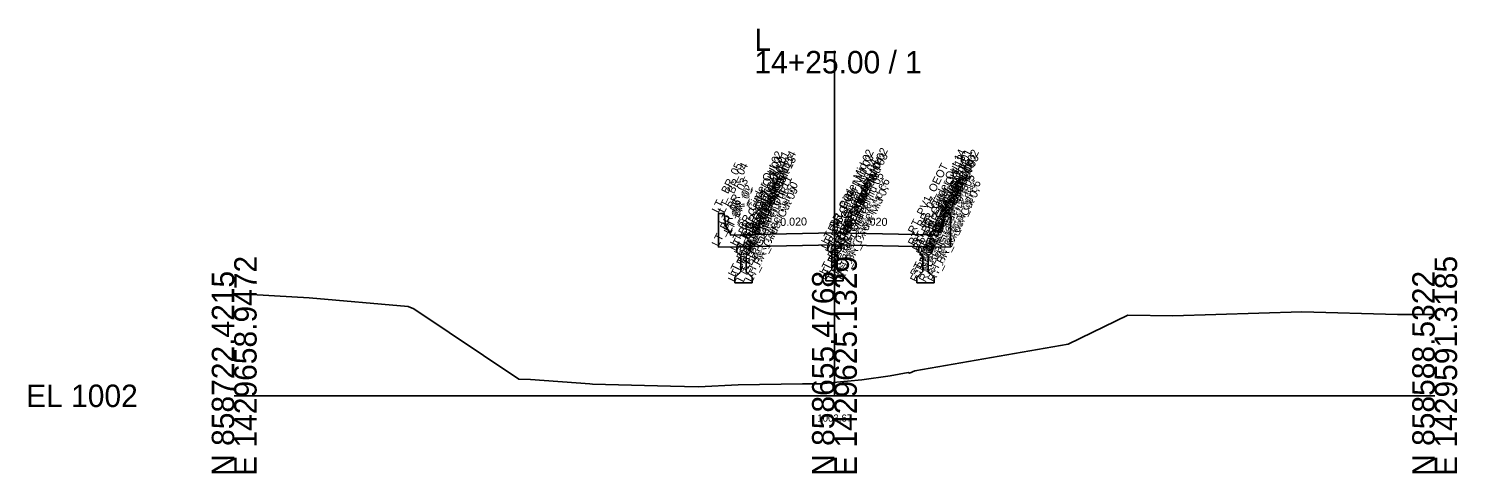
# Model space of a CAD drawing. Extents: x -26 to 153, y -10 to 13058.
# Drawn here: x -25.7 to 152.8, y 5490.3 to 5545.9 of the extents above; entities that cross this region are included whole.
import ezdxf

# ---------------------------------------------------------------- set-up
doc = ezdxf.new("R2010")
doc.units = 0
for name, color, linetype in [('Default', 7, 'Continuous'), ('Exist Cross Section Cell', 7, 'Continuous'), ('Exist XS Ground Line', 7, 'Continuous'), ('Prop CMT Concrete Structures', 7, 'Continuous'), ('Prop CMT Subgrade Daylight Point', 7, 'Continuous'), ('Prop XS Dump Level', 7, 'Continuous'), ('Prop XS SE Text', 7, 'Continuous')]:
    doc.layers.add(name, color=color, linetype=linetype)

msp = doc.modelspace()

# ---------------------------------------------------------------- linework, layer by layer
at = {"layer": 'Exist Cross Section Cell'}
for p, q in [((75, 5500), (75, 5543.08)), ((0, 5500), (75, 5500)), ((75, 5500), (150, 5500))]:
    msp.add_line(p, q, dxfattribs=at)
at = {"layer": 'Exist XS Ground Line'}
msp.add_lwpolyline([(0, 5512.79), (9.35, 5512.25), (21.72, 5511.16), (22.46, 5510.85), (35.55, 5502.07), (37.01, 5502.03), (44.44, 5501.49), (44.78, 5501.47), (54.52, 5501.19), (58.03, 5501.14), (62.99, 5501.38), (71.01, 5501.48), (73.39, 5501.51), (74.84, 5501.66), (78.42, 5502.01), (81.97, 5502.51), (84.22, 5502.92), (84.36, 5502.82), (85.04, 5503.11), (104.21, 5506.46), (111.64, 5510.06), (117.26, 5509.98), (133.39, 5510.5), (145.37, 5510.16), (149.53, 5510.15), (150, 5510.14)], dxfattribs=at)
at = {"layer": 'Prop CMT Concrete Structures'}
for points in [[(75, 5520.35), (65, 5520.15), (62, 5520.09), (61.99, 5520.34), (61.41, 5521.17), (61.24, 5522.76), (60.5, 5522.76), (60.5, 5518.56)], [(75, 5520.35), (85, 5520.15), (88, 5520.09), (88.01, 5520.34), (88.59, 5521.17), (88.76, 5522.76), (89.5, 5522.76), (89.5, 5518.56)], [(75, 5518.85), (75, 5520.35)], [(75, 5518.85), (75, 5520.35)], [(60.5, 5518.56), (65, 5518.65), (75, 5518.85)], [(64.46, 5518.64), (63.62, 5518.62), (62.79, 5518.61)], [(62.79, 5518.61), (62.79, 5517.96)], [(64.46, 5517.96), (64.46, 5518.64)], [(75, 5518.85), (74.17, 5518.83)], [(74.17, 5518.83), (74.17, 5518.18)], [(75, 5514.35), (75, 5518.85)], [(75, 5518.85), (75.83, 5518.83)], [(75, 5514.35), (75, 5518.85)], [(89.5, 5518.56), (85, 5518.65), (75, 5518.85)], [(75.83, 5518.83), (75.83, 5518.18)], [(85.54, 5518.64), (86.38, 5518.62), (87.21, 5518.61)], [(85.54, 5517.96), (85.54, 5518.64)], [(87.21, 5518.61), (87.21, 5517.96)], [(62.79, 5517.96), (63.29, 5517.46)], [(63.29, 5517.46), (63.29, 5515.54)], [(63.96, 5517.46), (64.46, 5517.96)], [(63.96, 5515.54), (63.96, 5517.46)], [(74.17, 5518.18), (74.67, 5517.68)], [(74.67, 5517.68), (74.67, 5515.77)], [(75.83, 5518.18), (75.33, 5517.68)], [(75.33, 5517.68), (75.33, 5515.77)], [(86.04, 5517.46), (85.54, 5517.96)], [(86.04, 5515.54), (86.04, 5517.46)], [(87.21, 5517.96), (86.71, 5517.46)], [(86.71, 5517.46), (86.71, 5515.54)], [(63.29, 5515.54), (62.54, 5514.79)], [(64.71, 5514.79), (63.96, 5515.54)], [(74.67, 5515.77), (73.92, 5515.02)], [(73.92, 5515.02), (73.92, 5514.35)], [(75.33, 5515.77), (76.08, 5515.02)], [(76.08, 5515.02), (76.08, 5514.35)], [(85.29, 5514.79), (86.04, 5515.54)], [(86.71, 5515.54), (87.46, 5514.79)], [(62.54, 5514.79), (62.54, 5514.12)], [(62.54, 5514.12), (63.62, 5514.12), (64.71, 5514.12)], [(64.71, 5514.12), (64.71, 5514.79)], [(73.92, 5514.35), (75, 5514.35)], [(76.08, 5514.35), (75, 5514.35)], [(85.29, 5514.12), (85.29, 5514.79)], [(87.46, 5514.12), (86.38, 5514.12), (85.29, 5514.12)], [(87.46, 5514.79), (87.46, 5514.12)]]:
    msp.add_lwpolyline(points, dxfattribs=at)

# ---------------------------------------------------------------- texts
at = {"layer": 'Default'}
msp.add_text('-', height=0.0001, dxfattribs=at).set_placement((0, 5500))
at = {"layer": 'Exist Cross Section Cell'}
for s, p in [('L', (65, 5543.08)), ('14+25.00 / 1', (65, 5540.28)), ('EL 1002', (-26, 5498.6))]:
    msp.add_text(s, height=2.8, dxfattribs=at).set_placement(p)
for s, p in [('E 1429658.9472', (2.8, 5490)), ('E 1429625.1329', (77.8, 5490)), ('E 1429591.3185', (152.8, 5490)), ('N 858722.4215', (0, 5490)), ('N 858655.4768', (75, 5490)), ('N 858588.5322', (150, 5490))]:
    msp.add_text(s, height=2.8, rotation=90, dxfattribs=at).set_placement(p)
at = {"layer": 'Prop CMT Subgrade Daylight Point'}
msp.add_text('1003.67', height=0.9, dxfattribs=at).set_placement((72.86, 5496.77))
at = {"layer": 'Prop XS Dump Level'}
for s, p in [('RT_BR_Girder Mid 02', (75.83, 5518.83)), ('LT_ BR_05', (60.5, 5522.76)), ('LT_BR_Girder Out 02', (62.79, 5518.61)), ('LT_BR_Girder Out 03', (62.79, 5517.96)), ('LT_BR_Girder Out 04', (63.29, 5517.46)), ('LT_BR_Girder Out 01', (63.62, 5518.62)), ('LT_BR_Girder Out 12', (63.96, 5517.46)), ('LT_BR_Girder Out 14', (64.46, 5518.64)), ('LT_BR_Girder Out 13', (64.46, 5517.96)), ('LT_BR_Girder Mid 02', (74.17, 5518.83)), ('LT_BR_Girder Mid 03', (74.17, 5518.18)), ('LT_BR_Girder Mid 04', (74.67, 5517.68)), ('RT_BR_Girder Mid 04', (75.33, 5517.68)), ('RT_BR_Girder Mid 03', (75.83, 5518.18)), ('RT_BR_Girder Out 14', (85.54, 5518.64)), ('RT_BR_Girder Out 13', (85.54, 5517.96)), ('RT_BR_Girder Out 12', (86.04, 5517.46)), ('RT_BR_Girder Out 01', (86.38, 5518.62)), ('RT_BR_Girder Out 04', (86.71, 5517.46)), ('RT_BR_Girder Out 02', (87.21, 5518.61)), ('RT_BR_Girder Out 03', (87.21, 5517.96)), ('RT_ BR_04', (88.76, 5522.76)), ('RT_ BR_05', (89.5, 5522.76)), ('LT_ BR_04', (61.24, 5522.76)), ('LT_BR_Girder Out 05', (63.29, 5515.54)), ('LT_BR_Girder Out 11', (63.96, 5515.54)), ('LT_PV1_OEOT', (65, 5520.15)), ('LT_BR_Girder Mid 05', (74.67, 5515.77)), ('RT_BR_Girder Mid 05', (75.33, 5515.77)), ('RT_PV1_OEOT', (85, 5520.15)), ('RT_BR_Girder Out 11', (86.04, 5515.54)), ('RT_BR_Girder Out 05', (86.71, 5515.54)), ('RT_BR_03', (88.59, 5521.17)), ('LT_BR_03', (61.41, 5521.17)), ('LT_BR_02', (61.99, 5520.34)), ('LT_BR_01', (62, 5520.09)), ('LT_BR_Girder Out 06', (62.54, 5514.79)), ('LT_BR_Girder Out 07', (62.54, 5514.12)), ('LT_BR_Girder Out 08', (63.62, 5514.12)), ('LT_BR_Girder Out 10', (64.71, 5514.79)), ('LT_BR_Girder Out 09', (64.71, 5514.12)), ('LT_BR_Girder Mid 06', (73.92, 5515.02)), ('LT_BR_Girder Mid 07', (73.92, 5514.35)), ('PV1_PGL', (75, 5520.35)), ('RT_BR_Girder Mid 06', (76.08, 5515.02)), ('RT_BR_Girder Mid 07', (76.08, 5514.35)), ('RT_BR_Girder Out 10', (85.29, 5514.79)), ('RT_BR_Girder Out 09', (85.29, 5514.12)), ('RT_BR_Girder Out 08', (86.38, 5514.12)), ('RT_BR_Girder Out 06', (87.46, 5514.79)), ('RT_BR_Girder Out 07', (87.46, 5514.12)), ('RT_BR_01', (88, 5520.09)), ('RT_BR_02', (88.01, 5520.34)), ('LT_BR_06', (60.5, 5518.56)), ('LT_BR_07', (65, 5518.65)), ('BR_Girder Mid 08', (75, 5514.35)), ('RT_BR_07', (85, 5518.65)), ('RT_BR_06', (89.5, 5518.56)), ('BR_PGL', (75, 5518.85))]:
    msp.add_text(s, height=1, rotation=63.5833, dxfattribs=at).set_placement(p)
at = {"layer": 'Prop XS SE Text'}
for rotation, p in [(1.1458, (68.23, 5521.22)), (358.8542, (78.27, 5521.29))]:
    msp.add_text('0.020', height=1, rotation=rotation, dxfattribs=at).set_placement(p)

doc.saveas('drawing.dxf')
